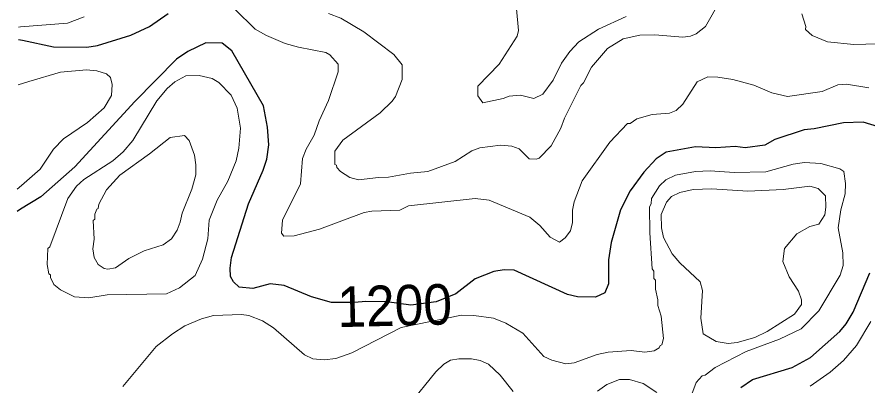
# Model space of a CAD drawing. Extents: x 598.3 to 623.2, y 6902.2 to 6930.1.
# Drawn here: x 598.503 to 600.179, y 6923.743 to 6924.47 of the extents above; entities that cross this region are included whole.
import ezdxf
from ezdxf.enums import TextEntityAlignment as Align

# ---------------------------------------------------------------- set-up
doc = ezdxf.new("R2010")
doc.units = 0
doc.header["$LTSCALE"] = 0.032
doc.layers.add('1', color=7, linetype='Continuous', lineweight=25)
doc.layers.add('2', color=7, linetype='Continuous', lineweight=13)
doc.layers.add('61', color=7, linetype='Continuous')

msp = doc.modelspace()

# ---------------------------------------------------------------- linework, layer by layer
at = {"layer": '1'}
for points in [[(598.5057, 6924.4261), (598.514, 6924.4244), (598.575, 6924.4118), (598.6405, 6924.411), (598.6613, 6924.4141), (598.7274, 6924.4342), (598.7642, 6924.4518), (598.8008, 6924.4775)], [(600.2001, 6924.2537), (600.1702, 6924.2628), (600.131, 6924.2619), (600.0733, 6924.2499), (600.0536, 6924.2482), (599.996, 6924.2291), (599.9762, 6924.2176), (599.9377, 6924.2127), (599.9179, 6924.215), (599.8795, 6924.2127), (599.8399, 6924.2142), (599.7817, 6924.2037), (599.762, 6924.1906), (599.7377, 6924.1646), (599.7108, 6924.1275), (599.6921, 6924.0903), (599.6732, 6924.0257), (599.6684, 6923.9915), (599.6682, 6923.9444), (599.6609, 6923.9269), (599.6423, 6923.918), (599.6071, 6923.9187), (599.5876, 6923.9236), (599.4824, 6923.9712), (599.4624, 6923.9722), (599.4425, 6923.9687), (599.4057, 6923.9542), (599.3671, 6923.925), (599.3288, 6923.9086), (599.279, 6923.9025), (599.2316, 6923.9086), (599.1903, 6923.9098), (599.1676, 6923.9077), (599.1224, 6923.9075), (599.0831, 6923.9187), (599.029, 6923.9409), (599.0016, 6923.9446), (598.9673, 6923.935), (598.9405, 6923.9379), (598.9295, 6923.9485), (598.9238, 6923.9587), (598.9228, 6923.9753), (598.9252, 6923.996), (598.959, 6924.1022), (598.988, 6924.1682), (598.9949, 6924.1902), (598.9988, 6924.2181), (598.9964, 6924.2534), (598.9883, 6924.2952), (598.926, 6924.4036), (598.907, 6924.419), (598.8747, 6924.4192), (598.8397, 6924.4022), (598.8172, 6924.3872), (598.7347, 6924.3038), (598.6165, 6924.1751), (598.5497, 6924.1157), (598.51, 6924.0913), (598.5029, 6924.087)], [(599.9286, 6923.7401), (599.9519, 6923.7561), (600.0302, 6923.7793), (600.066, 6923.7994), (600.1238, 6923.8505), (600.1363, 6923.8656), (600.1499, 6923.8888), (600.1829, 6923.9658)]]:
    msp.add_lwpolyline(points, dxfattribs=at)
at = {"layer": '2'}
for points in [[(599.8891, 6924.5038), (599.8591, 6924.4513), (599.8408, 6924.437), (599.8297, 6924.4326), (599.8149, 6924.4304), (599.7595, 6924.4352), (599.7296, 6924.4344), (599.6971, 6924.4273), (599.6662, 6924.4081), (599.6348, 6924.3716), (599.619, 6924.3407), (599.6138, 6924.3351), (599.5815, 6924.2707), (599.5741, 6924.2509), (599.5553, 6924.2161), (599.5315, 6924.192), (599.5258, 6924.19), (599.5117, 6924.1907), (599.492, 6924.2108), (599.4777, 6924.2157), (599.4556, 6924.2175), (599.4144, 6924.2127), (599.3988, 6924.2065), (599.3658, 6924.1857), (599.3124, 6924.1657), (599.2779, 6924.1624), (599.235, 6924.1544), (599.2148, 6924.1543), (599.1757, 6924.1495), (599.1588, 6924.1541), (599.1404, 6924.1658), (599.1331, 6924.1737), (599.1324, 6924.1784), (599.1292, 6924.1798), (599.1292, 6924.2062), (599.1449, 6924.2277), (599.2186, 6924.2816), (599.2418, 6924.3043), (599.2484, 6924.3136), (599.2619, 6924.3471), (599.2619, 6924.3758), (599.2454, 6924.3966), (599.1864, 6924.441), (599.1408, 6924.4679), (599.1165, 6924.4773)], [(598.9321, 6924.4855), (598.9723, 6924.4464), (598.9943, 6924.4338), (599.0315, 6924.4184), (599.0572, 6924.4107), (599.1112, 6924.4005), (599.1192, 6924.3957), (599.1356, 6924.3774), (599.1354, 6924.3623), (599.1167, 6924.3057), (599.0983, 6924.2658), (599.0881, 6924.2375), (599.0725, 6924.21), (599.0652, 6924.1913), (599.0611, 6924.1417), (599.026, 6924.0698), (599.024, 6924.0445), (599.0287, 6924.0385), (599.0489, 6924.0391), (599.0987, 6924.0524), (599.1869, 6924.0848), (599.2018, 6924.0879), (599.2571, 6924.0896), (599.2739, 6924.0983), (599.4054, 6924.1123), (599.4333, 6924.109), (599.5131, 6924.0756)], [(599.4871, 6924.4867), (599.491, 6924.4436), (599.4884, 6924.4326), (599.4531, 6924.3772), (599.4109, 6924.3337), (599.4109, 6924.315), (599.4207, 6924.301), (599.4605, 6924.3099), (599.4724, 6924.3146), (599.4951, 6924.3162), (599.5209, 6924.3097), (599.539, 6924.3179), (599.5592, 6924.3457), (599.5759, 6924.3791), (599.5922, 6924.402), (599.6098, 6924.4212), (599.6487, 6924.4464), (599.703, 6924.471)], [(598.6352, 6924.4707), (598.6021, 6924.4584), (598.51, 6924.4507), (598.5059, 6924.4504)], [(600.2692, 6924.4191), (600.1515, 6924.4158), (600.0998, 6924.4212), (600.0696, 6924.4338), (600.0564, 6924.4454), (600.0567, 6924.4516), (600.0488, 6924.4765)], [(598.505, 6924.3367), (598.5262, 6924.343), (598.5887, 6924.3616), (598.6397, 6924.3663), (598.6602, 6924.3639), (598.6793, 6924.3585), (598.687, 6924.351), (598.6903, 6924.3375), (598.6889, 6924.3159), (598.6744, 6924.2914), (598.6415, 6924.2621), (598.5947, 6924.2302), (598.5748, 6924.2096), (598.5484, 6924.1701), (598.5116, 6924.1382), (598.5033, 6924.131)], [(599.5131, 6924.0756), (599.5328, 6924.0592), (599.5531, 6924.0363), (599.5717, 6924.0265), (599.5827, 6924.0348), (599.593, 6924.0491), (599.597, 6924.0651), (599.5971, 6924.0896), (599.6004, 6924.1062), (599.6162, 6924.1473), (599.6709, 6924.2234), (599.7058, 6924.2603), (599.711, 6924.2607), (599.7239, 6924.2695), (599.7539, 6924.2781), (599.7883, 6924.2807), (599.8013, 6924.2859), (599.8144, 6924.2987), (599.8427, 6924.3424), (599.8641, 6924.3525), (599.8836, 6924.3518), (599.913, 6924.3469), (599.9546, 6924.3357), (599.9898, 6924.3207), (600.0211, 6924.3139), (600.0889, 6924.3235), (600.1203, 6924.3365), (600.1369, 6924.338), (600.1813, 6924.3308)], [(599.8286, 6923.7164), (599.8412, 6923.7497), (599.8529, 6923.7632), (599.8587, 6923.7646), (599.8786, 6923.7794), (599.9397, 6923.8107), (600.0048, 6923.8352), (600.0476, 6923.856), (600.0823, 6923.8915), (600.1248, 6923.9617), (600.1304, 6923.9806), (600.1297, 6924.0057), (600.1209, 6924.0545), (600.1261, 6924.0905), (600.1345, 6924.1219), (600.1353, 6924.142), (600.1321, 6924.1659), (600.1239, 6924.1709), (600.0863, 6924.1818), (600.0546, 6924.1834), (600.032, 6924.1801), (599.9781, 6924.1649), (599.9159, 6924.1641), (599.8686, 6924.1673), (599.8397, 6924.1656), (599.8004, 6924.1589), (599.7809, 6924.1494), (599.7688, 6924.1375), (599.7526, 6924.1125), (599.7524, 6924.1021), (599.7492, 6924.0963), (599.7493, 6924.0452), (599.7542, 6923.9741), (599.7573, 6923.9696), (599.7574, 6923.9547), (599.7605, 6923.9517), (599.7607, 6923.934), (599.7654, 6923.9131), (599.7655, 6923.9016), (599.7719, 6923.8807), (599.7766, 6923.8365), (599.7734, 6923.8242)], [(599.7734, 6923.8242), (599.77, 6923.8228), (599.768, 6923.818), (599.7584, 6923.8126), (599.7397, 6923.8095), (599.713, 6923.8128), (599.6673, 6923.8095), (599.6457, 6923.8054), (599.6006, 6923.7885), (599.5842, 6923.7869), (599.5567, 6923.7937), (599.5409, 6923.801), (599.4997, 6923.8469), (599.4662, 6923.8669), (599.4414, 6923.8767), (599.4031, 6923.8823), (599.3785, 6923.8824), (599.26, 6923.8583), (599.1623, 6923.8083), (599.1311, 6923.7974), (599.1081, 6923.7949), (599.0855, 6923.7966), (599.0696, 6923.8044), (599.0083, 6923.8574), (598.9862, 6923.8717), (598.9598, 6923.8822), (598.9453, 6923.884), (598.89, 6923.8823), (598.8663, 6923.8756), (598.8332, 6923.8613), (598.8092, 6923.8461), (598.7773, 6923.8211), (598.7112, 6923.7421)], [(600.1852, 6923.8704), (600.1565, 6923.8231), (600.1311, 6923.7931), (600.1046, 6923.7704), (600.0652, 6923.7428)], [(599.2745, 6923.7054), (599.3279, 6923.771), (599.344, 6923.7862), (599.3569, 6923.7939), (599.3731, 6923.7965), (599.3985, 6923.7965), (599.4156, 6923.7933), (599.4319, 6923.7859), (599.4549, 6923.7646), (599.4803, 6923.7321)], [(599.6466, 6923.7328), (599.6648, 6923.7462), (599.6897, 6923.756), (599.7094, 6923.7559), (599.7366, 6923.7478), (599.7634, 6923.7305)]]:
    msp.add_lwpolyline(points, dxfattribs=at)
for points in [[(598.8356, 6924.3542), (598.862, 6924.355), (598.8873, 6924.3488), (598.9006, 6924.3415), (598.9249, 6924.3165), (598.9363, 6924.2909), (598.9429, 6924.2514), (598.9397, 6924.212), (598.9349, 6924.187), (598.9182, 6924.1467), (598.897, 6924.1093), (598.8815, 6924.0701), (598.8786, 6924.0331), (598.8686, 6923.9927), (598.8536, 6923.9605), (598.8232, 6923.9365), (598.7974, 6923.9245), (598.6804, 6923.9228), (598.6447, 6923.9166), (598.6162, 6923.9187), (598.5887, 6923.9324), (598.5757, 6923.9429), (598.5691, 6923.9571), (598.569, 6923.9622), (598.5658, 6923.9644), (598.5626, 6923.9822), (598.5634, 6924.014), (598.5674, 6924.0172), (598.6032, 6924.1125), (598.6204, 6924.1368), (598.6346, 6924.1502), (598.6918, 6924.1866), (598.7123, 6924.2045), (598.7309, 6924.2272), (598.7786, 6924.3049), (598.7985, 6924.3295), (598.8138, 6924.3423)], [(598.7637, 6924.2003), (598.8048, 6924.2327), (598.8326, 6924.2368), (598.8418, 6924.2269), (598.8524, 6924.1978), (598.8555, 6924.1789), (598.8555, 6924.1595), (598.847, 6924.131), (598.8281, 6924.0834), (598.8245, 6924.0661), (598.8182, 6924.0505), (598.8071, 6924.0332), (598.7906, 6924.0214), (598.7536, 6924.0094), (598.7233, 6923.9943), (598.6972, 6923.976), (598.6816, 6923.973), (598.6745, 6923.9747), (598.6629, 6923.9822), (598.6549, 6923.996), (598.6524, 6924.0133), (598.6547, 6924.0324), (598.6532, 6924.069), (598.6563, 6924.0717), (598.6565, 6924.0815), (598.6599, 6924.0913), (598.6629, 6924.093), (598.6638, 6924.1016), (598.679, 6924.1298), (598.7052, 6924.1584)], [(599.8087, 6923.9856), (599.7937, 6924.0038), (599.7763, 6924.036), (599.7726, 6924.0549), (599.772, 6924.0813), (599.7823, 6924.1054), (599.7926, 6924.1163), (599.8086, 6924.1242), (599.8348, 6924.13), (599.8717, 6924.1317), (599.9428, 6924.1269), (600.0121, 6924.1304), (600.0648, 6924.1366), (600.0811, 6924.1324), (600.0957, 6924.1177), (600.0965, 6924.0955), (600.0942, 6924.0807), (600.0826, 6924.0621), (600.0649, 6924.0571), (600.0395, 6924.0429), (600.0148, 6924.014), (600.0117, 6923.9884), (600.0244, 6923.9584), (600.0426, 6923.9301), (600.0487, 6923.9131), (600.0487, 6923.9037), (600.0347, 6923.8845), (599.9805, 6923.8506), (599.9566, 6923.8387), (599.9216, 6923.8287), (599.904, 6923.8265), (599.8804, 6923.831), (599.8547, 6923.8458), (599.8504, 6923.8765), (599.8536, 6923.9314), (599.8489, 6923.9484)]]:
    msp.add_lwpolyline(points, close=True, dxfattribs=at)

# ---------------------------------------------------------------- texts
at = {"layer": '61', "width": 0.95}
msp.add_text('1200', height=0.08, rotation=1.409, dxfattribs=at).set_placement((599.2478, 6923.8617), align=Align.CENTER)

doc.saveas('drawing.dxf')
